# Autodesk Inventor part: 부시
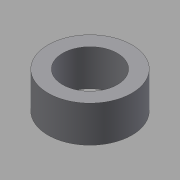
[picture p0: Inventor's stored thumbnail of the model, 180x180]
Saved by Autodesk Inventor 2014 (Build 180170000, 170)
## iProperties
Created: 2015-09
Part Number: 부시
Document SubType Name: Modeling
Designer: mduedu
Density: 1 g/cm^3
Material: 스테인리스강
Appearance: Default
Author: mduedu
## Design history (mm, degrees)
node "작업 평면1"
node "작업 평면2"
sketch "스케치1"
  geometry: C1 r 7.5 at (0, 0); C2 r 11.5 at (0, 0); 1 further point
  constraints: 2 centre point, 2 coincident
  dimensions: "d0" = 15 diameter of C1; "d1" = 23 diameter of C2
extrude "돌출1" new body sketch "스케치1" stored distance "d2" = 9.85; taper "d3" = 0 deg
node "솔리드1"
